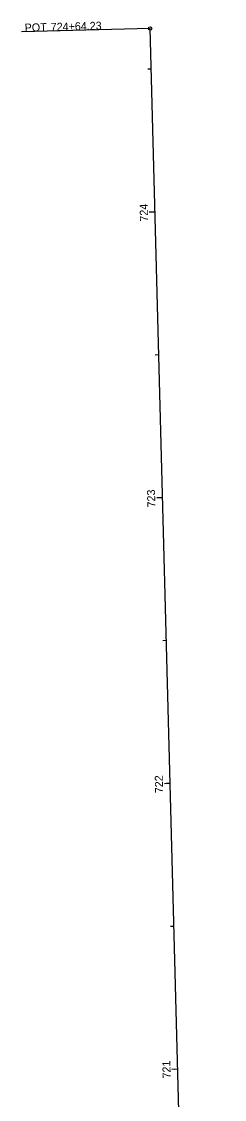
# Model space of a CAD drawing. Extents: x 2045805 to 2050091, y 455249 to 458900.
# Drawn here: x 2047542.3 to 2047613.4, y 458523.3 to 458900.4 of the extents above; entities that cross this region are included whole.
import ezdxf

# ---------------------------------------------------------------- set-up
doc = ezdxf.new("R2010")
doc.units = 0
for name, color, linetype in [('GE_P_Alignment_100_Bearings', 7, 'Continuous'), ('GE_P_Alignment_100_Cardinal_Points', 7, 'Continuous'), ('GE_P_Alignment_100_Distances', 7, 'Continuous'), ('GE_P_Alignment_100_Stations', 7, 'Continuous'), ('PF_P_Grade_Line', 7, 'Continuous'), ('PV_P_EOP', 7, 'Continuous')]:
    doc.layers.add(name, color=color, linetype=linetype)

msp = doc.modelspace()

# ---------------------------------------------------------------- linework, layer by layer
at = {"layer": 'GE_P_Alignment_100_Bearings'}
msp.add_line((2047587.33, 458898), (2047542.35, 458896.81), dxfattribs=at)
msp.add_circle((2047587.33, 458898), 0.6, dxfattribs=at)
at = {"layer": 'GE_P_Alignment_100_Cardinal_Points'}
for p, q in [((2047587.71, 458883.77), (2047586.51, 458883.74)), ((2047589.03, 458833.79), (2047587.04, 458833.73)), ((2047590.36, 458783.81), (2047589.16, 458783.77)), ((2047591.68, 458733.82), (2047589.68, 458733.77)), ((2047593.01, 458683.84), (2047591.81, 458683.81)), ((2047594.33, 458633.86), (2047592.33, 458633.8)), ((2047595.65, 458583.88), (2047594.45, 458583.84)), ((2047596.98, 458533.89), (2047594.98, 458533.84))]:
    msp.add_line(p, q, dxfattribs=at)
at = {"layer": 'GE_P_Alignment_100_Distances'}
msp.add_line((2047587.33, 458898), (2047542.35, 458896.81), dxfattribs=at)
msp.add_circle((2047587.33, 458898), 0.6, dxfattribs=at)
at = {"layer": 'GE_P_Alignment_100_Stations'}
for p, q in [((2047589.03, 458833.79), (2047587.83, 458833.76)), ((2047591.68, 458733.82), (2047590.48, 458733.79)), ((2047594.33, 458633.86), (2047593.13, 458633.83)), ((2047596.98, 458533.89), (2047595.78, 458533.86))]:
    msp.add_line(p, q, dxfattribs=at)
at = {"layer": 'PF_P_Grade_Line'}
msp.add_line((2047587.33, 458898), (2047542.35, 458896.81), dxfattribs=at)
msp.add_circle((2047587.33, 458898), 0.6, dxfattribs=at)
at = {"layer": 'PV_P_EOP'}
msp.add_line((2047613.37, 457914.72), (2047587.33, 458898), dxfattribs=at)

# ---------------------------------------------------------------- texts
at = {"layer": 'GE_P_Alignment_100_Bearings'}
for s, p in [('POT', (2047543.48, 458896.88)), ('724+64.23', (2047552.61, 458897.12))]:
    msp.add_text(s, height=2.8, rotation=1.5169, dxfattribs=at).set_placement(p)
at = {"layer": 'GE_P_Alignment_100_Cardinal_Points'}
for s, p in [('724', (2047586.62, 458830.48)), ('723', (2047589.22, 458730.49)), ('722', (2047591.92, 458630.52)), ('721', (2047594.56, 458530.72))]:
    msp.add_text(s, height=2.8, rotation=91.5169, dxfattribs=at).set_placement(p)
at = {"layer": 'GE_P_Alignment_100_Distances'}
for s, p in [('POT', (2047543.48, 458896.88)), ('724+64.23', (2047552.61, 458897.12))]:
    msp.add_text(s, height=2.8, rotation=1.5169, dxfattribs=at).set_placement(p)
at = {"layer": 'PF_P_Grade_Line'}
for s, p in [('POT', (2047543.48, 458896.88)), ('724+64.23', (2047552.61, 458897.12))]:
    msp.add_text(s, height=2.8, rotation=1.5169, dxfattribs=at).set_placement(p)

doc.saveas('drawing.dxf')
